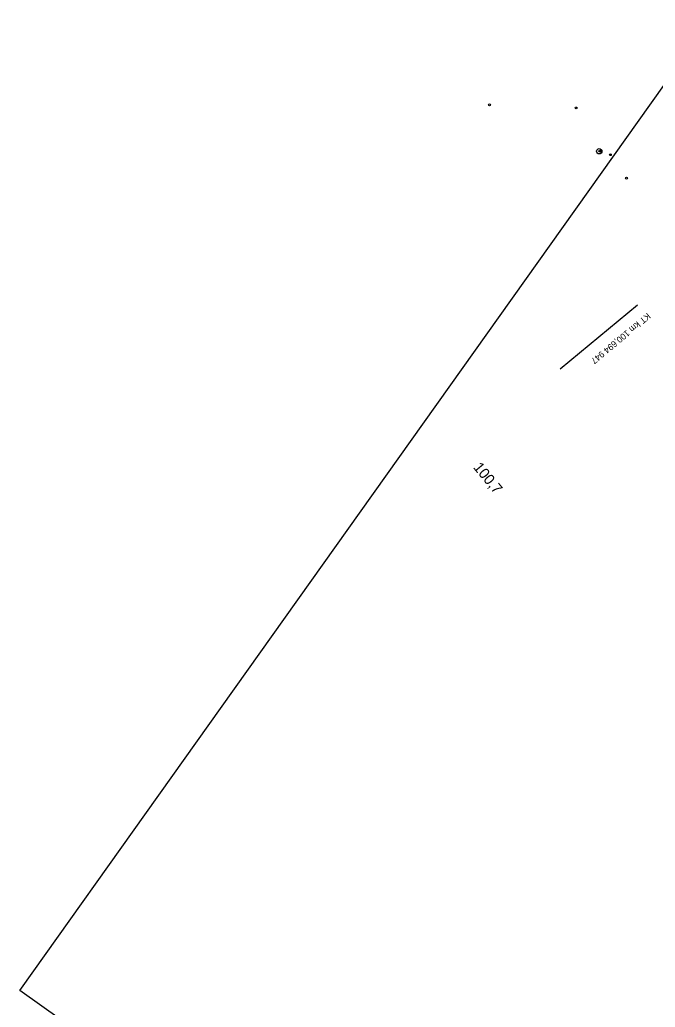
# Model space of a CAD drawing. Extents: x -505028 to -503155, y -1080361 to -1077947.
# Drawn here: x -504654.1 to -504533.8, y -1078872.2 to -1078685.3 of the extents above; entities that cross this region are included whole.
import ezdxf

# ---------------------------------------------------------------- set-up
doc = ezdxf.new("R2010")
doc.units = 0
for name, color, linetype in [('C3D-TRASA-POPIS', 7, 'Continuous'), ('C3D_Trasa-Popisy trasy', 7, 'Continuous'), ('Vrstva 24', 7, 'Continuous'), ('Vrstva 36', 7, 'Continuous'), ('Vrstva 63', 7, 'Continuous'), ('Zabzař nadzemní_1', 7, 'Continuous'), ('ŽKN stavba druh', 7, 'Continuous')]:
    doc.layers.add(name, color=color, linetype=linetype)

# ---------------------------------------------------------------- blocks, each defined once
blk = doc.blocks.new('C053_18')
at = {"layer": 'Zabzař nadzemní_1'}
blk.add_line((-0.5, 0), (0.5, 0), dxfattribs=at)
blk.add_circle((0, 0), 5, dxfattribs=at)
blk = doc.blocks.new('C045')
at = {"layer": 'ŽKN stavba druh'}
blk.add_circle((0, 0), 1.75, dxfattribs=at)

msp = doc.modelspace()

# ---------------------------------------------------------------- linework, layer by layer
at = {"layer": 'C3D-TRASA-POPIS'}
msp.add_line((-504537.19, -1078739.3), (-504551.83, -1078751.4), dxfattribs=at)
at = {"layer": 'Vrstva 63'}
msp.add_lwpolyline([(-504483.07, -1078990.76), (-504654.14, -1078868.97), (-504481.9, -1078627.02), (-504310.82, -1078748.81)], close=True, dxfattribs=at)

# ---------------------------------------------------------------- block references
at = {"layer": 'Vrstva 24', "xscale": 0.1, "yscale": 0.10000000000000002}
for p in [(-504565.21, -1078701.39), (-504565.21, -1078701.39), (-504565.21, -1078701.39), (-504565.21, -1078701.39), (-504548.81, -1078701.97), (-504548.81, -1078701.97), (-504548.81, -1078701.97), (-504548.81, -1078701.97), (-504544.35, -1078710.16), (-504544.35, -1078710.16), (-504544.35, -1078710.16), (-504544.35, -1078710.16), (-504542.33, -1078710.82), (-504542.33, -1078710.82), (-504542.33, -1078710.82), (-504542.33, -1078710.82), (-504539.26, -1078715.25), (-504539.26, -1078715.25), (-504539.26, -1078715.25), (-504539.26, -1078715.25)]:
    msp.add_blockref('C045', p, dxfattribs=at)
at = {"layer": 'Vrstva 36', "xscale": 0.1, "yscale": 0.09999999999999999, "rotation": -49.77233946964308}
msp.add_blockref('C053_18', (-504544.43, -1078710.17), dxfattribs=at)
msp.add_blockref('C053_18', (-504544.43, -1078710.17), dxfattribs=at)

# ---------------------------------------------------------------- texts
at = {"layer": 'C3D-TRASA-POPIS'}
msp.add_text('KT km 100,694 947', height=1.2, rotation=219.599, dxfattribs=at).set_placement((-504535.34, -1078740.68))
at = {"layer": 'C3D_Trasa-Popisy trasy'}
msp.add_text('100,7', height=2, rotation=309.599, dxfattribs=at).set_placement((-504568.39, -1078770.04))

doc.saveas('drawing.dxf')
